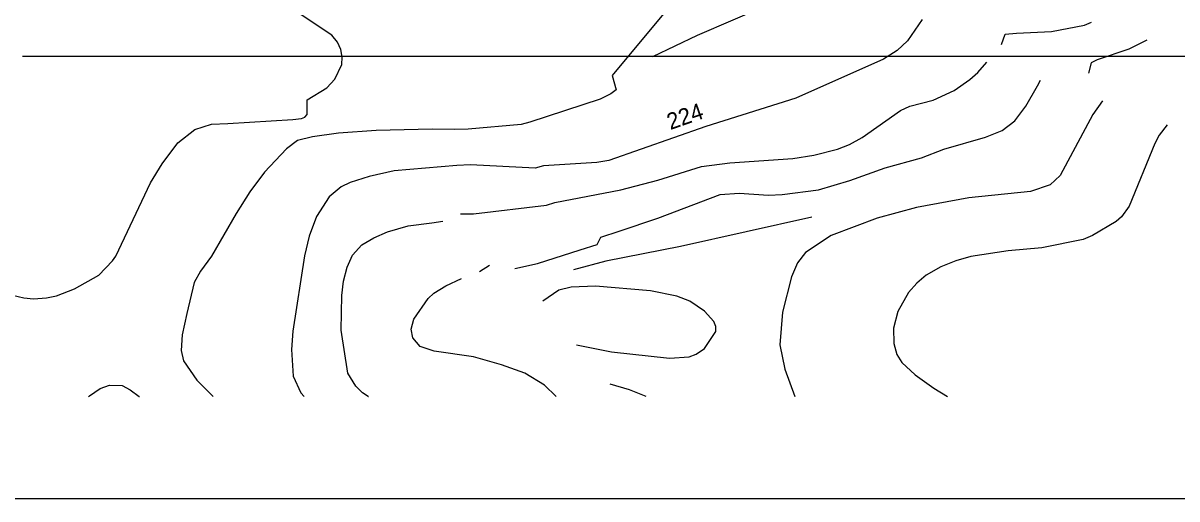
# Model space of a CAD drawing. Extents: x -662500 to -653478, y -1056827 to -1049993.
# Drawn here: x -659830 to -659128, y -1054269 to -1053980 of the extents above; entities that cross this region are included whole.
import ezdxf

# ---------------------------------------------------------------- set-up
doc = ezdxf.new("R2010")
doc.units = 0
for name, color, linetype in [('Vrstva 24', 7, 'Continuous'), ('Vrstva 7', 7, 'Continuous'), ('Vrstva 9', 7, 'Continuous')]:
    doc.layers.add(name, color=color, linetype=linetype)

msp = doc.modelspace()

# ---------------------------------------------------------------- linework, layer by layer
at = {"layer": 'Vrstva 24'}
for points in [[(-659446.58, -1054000), (-659419.5, -1053987), (-659376, -1053968.5), (-659341.5, -1053961)], [(-659446.58, -1054000), (-659830.33, -1054000)], [(-659029.99, -1054000), (-659446.58, -1054000)]]:
    msp.add_lwpolyline(points, dxfattribs=at)
at = {"layer": 'Vrstva 7'}
for p, q in [((-659431.99, -1053964.25), (-659471.32, -1054011.6)), ((-659642.01, -1053987.17), (-659674.04, -1053965.75)), ((-659282.58, -1053977.56), (-659291.58, -1053990.63)), ((-659183.94, -1053981.09), (-659179.67, -1053979.24)), ((-659234.42, -1053992.83), (-659232.23, -1053986.49)), ((-659232.23, -1053986.49), (-659225.23, -1053985.94)), ((-659225.23, -1053985.94), (-659203.88, -1053984.8)), ((-659203.88, -1053984.8), (-659183.94, -1053981.09)), ((-659638.56, -1053991.25), (-659642.01, -1053987.17)), ((-659636.59, -1053995.86), (-659638.56, -1053991.25)), ((-659291.58, -1053990.63), (-659297.85, -1053996.47)), ((-659146.03, -1053990.18), (-659156.89, -1053995.62)), ((-659635.74, -1054000.47), (-659636.59, -1053995.86)), ((-659635.8, -1054004.89), (-659635.74, -1054000.47)), ((-659297.85, -1053996.47), (-659306.11, -1054001.6)), ((-659156.89, -1053995.62), (-659176.06, -1054002.09)), ((-659640.2, -1054013.87), (-659635.8, -1054004.89)), ((-659306.11, -1054001.6), (-659359.64, -1054025.52)), ((-659248.87, -1054009.85), (-659243.29, -1054003.55)), ((-659179.83, -1054003.99), (-659181.53, -1054010.16)), ((-659176.06, -1054002.09), (-659179.83, -1054003.99)), ((-659645.06, -1054019.06), (-659640.2, -1054013.87)), ((-659471.32, -1054011.6), (-659468.87, -1054020.36)), ((-659263.11, -1054020.82), (-659253.57, -1054014.13)), ((-659253.57, -1054014.13), (-659248.87, -1054009.85)), ((-659212.46, -1054017.94), (-659210.61, -1054014.39)), ((-659656.96, -1054026.48), (-659645.06, -1054019.06)), ((-659468.87, -1054020.36), (-659472.12, -1054022.78)), ((-659275.92, -1054026.66), (-659263.11, -1054020.82)), ((-659219.54, -1054030.36), (-659212.46, -1054017.94)), ((-659656.92, -1054035.36), (-659656.96, -1054026.48)), ((-659478.72, -1054026.05), (-659521.42, -1054039.99)), ((-659472.12, -1054022.78), (-659478.72, -1054026.05)), ((-659359.64, -1054025.52), (-659414.32, -1054042.6)), ((-659290.16, -1054030.36), (-659275.92, -1054026.66)), ((-659172.97, -1054027.02), (-659178.82, -1054035.48)), ((-659658.39, -1054037.01), (-659656.92, -1054035.36)), ((-659319.2, -1054049.44), (-659295.85, -1054032.92)), ((-659295.85, -1054032.92), (-659290.16, -1054030.36)), ((-659226.37, -1054039.33), (-659219.54, -1054030.36)), ((-659178.82, -1054035.48), (-659198.61, -1054072.5)), ((-659725.31, -1054044.51), (-659715.27, -1054041.28)), ((-659715.27, -1054041.28), (-659705.34, -1054040.84)), ((-659705.34, -1054040.84), (-659665.75, -1054038.5)), ((-659665.75, -1054038.5), (-659660.47, -1054037.88)), ((-659660.47, -1054037.88), (-659658.39, -1054037.01)), ((-659526.81, -1054041.44), (-659559.09, -1054044.35)), ((-659521.42, -1054039.99), (-659526.81, -1054041.44)), ((-659414.32, -1054042.6), (-659473.37, -1054063.38)), ((-659233.92, -1054045.17), (-659226.37, -1054039.33)), ((-659133.6, -1054041.76), (-659138.38, -1054048.01)), ((-659735.79, -1054052.57), (-659725.31, -1054044.51)), ((-659653.8, -1054049.01), (-659662.91, -1054051.29)), ((-659637.85, -1054046.73), (-659653.8, -1054049.01)), ((-659615.07, -1054045.17), (-659637.85, -1054046.73)), ((-659580.9, -1054044.31), (-659615.07, -1054045.17)), ((-659567.44, -1054044.52), (-659580.9, -1054044.31)), ((-659559.09, -1054044.35), (-659567.44, -1054044.52)), ((-659326.89, -1054053.71), (-659319.2, -1054049.44)), ((-659269.51, -1054056.56), (-659244.03, -1054049.15)), ((-659244.03, -1054049.15), (-659233.92, -1054045.17)), ((-659138.38, -1054048.01), (-659141.09, -1054053.14)), ((-659745.28, -1054065.47), (-659735.79, -1054052.57)), ((-659669.6, -1054056.27), (-659682.99, -1054070.51)), ((-659662.91, -1054051.29), (-659669.6, -1054056.27)), ((-659348.54, -1054060.12), (-659334.3, -1054056.56)), ((-659334.3, -1054056.56), (-659326.89, -1054053.71)), ((-659283.04, -1054061.68), (-659269.51, -1054056.56)), ((-659141.09, -1054053.14), (-659156.61, -1054091.3)), ((-659473.37, -1054063.38), (-659480.66, -1054064.65)), ((-659399.79, -1054064.81), (-659361.35, -1054062.25)), ((-659361.35, -1054062.25), (-659348.54, -1054060.12)), ((-659305.25, -1054067.95), (-659283.04, -1054061.68)), ((-659752.36, -1054077.09), (-659745.28, -1054065.47)), ((-659682.99, -1054070.51), (-659691.79, -1054082.38)), ((-659603.97, -1054069.66), (-659619.34, -1054073.07)), ((-659565.93, -1054066.43), (-659603.97, -1054069.66)), ((-659557.66, -1054065.94), (-659565.93, -1054066.43)), ((-659518.28, -1054068.13), (-659557.66, -1054065.94)), ((-659513.11, -1054066.6), (-659518.28, -1054068.13)), ((-659480.66, -1054064.65), (-659513.11, -1054066.6)), ((-659443.65, -1054075.35), (-659416.88, -1054067.09)), ((-659416.88, -1054067.09), (-659399.79, -1054064.81)), ((-659326.61, -1054075.64), (-659305.25, -1054067.95)), ((-659773.34, -1054121.59), (-659752.36, -1054077.09)), ((-659630.73, -1054076.77), (-659636.29, -1054079.48)), ((-659619.34, -1054073.07), (-659630.73, -1054076.77)), ((-659466.14, -1054081.33), (-659443.65, -1054075.35)), ((-659345.69, -1054081.33), (-659326.61, -1054075.64)), ((-659198.61, -1054072.5), (-659204.73, -1054078.2)), ((-659691.79, -1054082.38), (-659700.22, -1054095.57)), ((-659636.29, -1054079.48), (-659643.55, -1054085.6)), ((-659506.19, -1054089.05), (-659466.14, -1054081.33)), ((-659443.5, -1054098.42), (-659405.63, -1054084.03)), ((-659405.63, -1054084.03), (-659394.1, -1054083.32)), ((-659394.1, -1054083.32), (-659376.16, -1054084.46)), ((-659376.16, -1054084.46), (-659367.9, -1054084.18)), ((-659367.9, -1054084.18), (-659345.69, -1054081.33)), ((-659216.69, -1054082.33), (-659254.28, -1054086.17)), ((-659204.73, -1054078.2), (-659216.69, -1054082.33)), ((-659643.55, -1054085.6), (-659651.24, -1054097.56)), ((-659555.67, -1054095.84), (-659511.35, -1054090.69)), ((-659511.35, -1054090.69), (-659506.19, -1054089.05)), ((-659254.28, -1054086.17), (-659286.17, -1054092.01)), ((-659156.61, -1054091.3), (-659161.31, -1054097.7)), ((-659700.22, -1054095.57), (-659715.18, -1054121.59)), ((-659651.24, -1054097.56), (-659655.79, -1054109.52)), ((-659563.56, -1054095.9), (-659555.67, -1054095.84)), ((-659467.07, -1054106.44), (-659443.5, -1054098.42)), ((-659349.82, -1054097.85), (-659429.69, -1054115.79)), ((-659310.09, -1054098.42), (-659338, -1054109.09)), ((-659286.17, -1054092.01), (-659310.09, -1054098.42)), ((-659161.31, -1054097.7), (-659164.58, -1054100.55)), ((-659608.1, -1054106.82), (-659595.42, -1054103.11)), ((-659595.42, -1054103.11), (-659581.19, -1054101.26)), ((-659581.19, -1054101.26), (-659574.44, -1054100.4)), ((-659164.58, -1054100.55), (-659179.1, -1054109.09)), ((-659655.79, -1054109.52), (-659658.64, -1054121.48)), ((-659623.76, -1054114.65), (-659616.5, -1054110.38)), ((-659616.5, -1054110.38), (-659608.1, -1054106.82)), ((-659480.55, -1054114.56), (-659478.32, -1054110.13)), ((-659478.32, -1054110.13), (-659467.07, -1054106.44)), ((-659338, -1054109.09), (-659353.66, -1054119.35)), ((-659184.66, -1054111.52), (-659209.86, -1054116.5)), ((-659179.1, -1054109.09), (-659184.66, -1054111.52)), ((-659629.31, -1054121.05), (-659623.76, -1054114.65)), ((-659516.83, -1054126.04), (-659490.92, -1054117.78)), ((-659490.92, -1054117.78), (-659480.55, -1054114.56)), ((-659429.69, -1054115.79), (-659475.26, -1054124.61)), ((-659353.66, -1054119.35), (-659358.65, -1054125.75)), ((-659230.36, -1054118.49), (-659253.14, -1054121.91)), ((-659209.86, -1054116.5), (-659230.36, -1054118.49)), ((-659783.83, -1054133.21), (-659775.46, -1054124.57)), ((-659775.46, -1054124.57), (-659773.34, -1054121.59)), ((-659715.18, -1054121.59), (-659721.91, -1054130.72)), ((-659658.64, -1054121.48), (-659665.62, -1054167.33)), ((-659632.58, -1054128.32), (-659629.31, -1054121.05)), ((-659530.64, -1054129.19), (-659516.83, -1054126.04)), ((-659475.26, -1054124.61), (-659494.97, -1054129.88)), ((-659358.65, -1054125.75), (-659362.2, -1054134.15)), ((-659262.25, -1054124.47), (-659271.37, -1054128.17)), ((-659253.14, -1054121.91), (-659262.25, -1054124.47)), ((-659798.57, -1054141.57), (-659783.83, -1054133.21)), ((-659721.91, -1054130.72), (-659725.67, -1054137.71)), ((-659634.86, -1054136.86), (-659632.58, -1054128.32)), ((-659552.12, -1054130.93), (-659546.03, -1054127.16)), ((-659280.19, -1054133.3), (-659285.89, -1054138.14)), ((-659271.37, -1054128.17), (-659280.19, -1054133.3)), ((-659725.67, -1054137.71), (-659730.28, -1054156.57)), ((-659635.86, -1054145.69), (-659634.86, -1054136.86)), ((-659579.9, -1054144.26), (-659572.64, -1054139.71)), ((-659572.64, -1054139.71), (-659563.14, -1054135.23)), ((-659496.33, -1054140.42), (-659503.73, -1054142.27)), ((-659481.52, -1054139.99), (-659496.33, -1054140.42)), ((-659447.92, -1054142.84), (-659481.52, -1054139.99)), ((-659362.2, -1054134.15), (-659367.61, -1054155.65)), ((-659285.89, -1054138.14), (-659291.01, -1054143.83)), ((-659836.26, -1054145.4), (-659829.46, -1054146.96)), ((-659829.46, -1054146.96), (-659823.51, -1054147.52)), ((-659823.51, -1054147.52), (-659815.57, -1054147.1)), ((-659815.57, -1054147.1), (-659809.48, -1054145.82)), ((-659809.48, -1054145.82), (-659798.57, -1054141.57)), ((-659636.29, -1054166.76), (-659635.86, -1054145.69)), ((-659592.15, -1054159.93), (-659583.32, -1054147.4)), ((-659583.32, -1054147.4), (-659579.9, -1054144.26)), ((-659503.73, -1054142.27), (-659513.62, -1054149.02)), ((-659431.97, -1054145.97), (-659447.92, -1054142.84)), ((-659424, -1054149.1), (-659431.97, -1054145.97)), ((-659291.01, -1054143.83), (-659297.56, -1054155.37)), ((-659415.17, -1054155.08), (-659424, -1054149.1)), ((-659409.47, -1054161.49), (-659415.17, -1054155.08)), ((-659730.28, -1054156.57), (-659733.09, -1054169.49)), ((-659593.71, -1054166.19), (-659592.15, -1054159.93)), ((-659408.19, -1054164.48), (-659409.47, -1054161.49)), ((-659367.61, -1054155.65), (-659369.32, -1054175.59)), ((-659297.56, -1054155.37), (-659300.15, -1054165.42)), ((-659665.62, -1054167.33), (-659666.61, -1054178.43)), ((-659632.3, -1054192.81), (-659636.29, -1054166.76)), ((-659592.58, -1054171.46), (-659593.71, -1054166.19)), ((-659415.17, -1054177.86), (-659408.19, -1054167.61)), ((-659408.19, -1054167.61), (-659408.19, -1054164.48)), ((-659300.15, -1054165.42), (-659299.84, -1054174.73)), ((-659733.09, -1054169.49), (-659733.77, -1054179.11)), ((-659588.31, -1054176.58), (-659592.58, -1054171.46)), ((-659493.11, -1054175.7), (-659471.84, -1054179.86)), ((-659369.32, -1054175.59), (-659366.19, -1054190.39)), ((-659299.84, -1054174.73), (-659298.13, -1054181.57)), ((-659733.77, -1054179.11), (-659732.32, -1054185.33)), ((-659666.61, -1054178.43), (-659665.47, -1054194.67)), ((-659579.76, -1054179.43), (-659588.31, -1054176.58)), ((-659555.84, -1054182.85), (-659579.76, -1054179.43)), ((-659538.76, -1054187.83), (-659555.84, -1054182.85)), ((-659471.84, -1054179.86), (-659436.53, -1054183.84)), ((-659436.53, -1054183.84), (-659424.57, -1054182.99)), ((-659424.57, -1054182.99), (-659420.3, -1054181.28)), ((-659420.3, -1054181.28), (-659415.17, -1054177.86)), ((-659298.13, -1054181.57), (-659295, -1054186.41)), ((-659732.32, -1054185.33), (-659724.19, -1054197.22)), ((-659524.52, -1054192.96), (-659538.76, -1054187.83)), ((-659295, -1054186.41), (-659287.03, -1054193.95)), ((-659724.19, -1054197.22), (-659714.21, -1054207.12)), ((-659665.47, -1054194.67), (-659660.78, -1054204.92)), ((-659627.32, -1054200.79), (-659632.3, -1054192.81)), ((-659512.55, -1054200.11), (-659524.52, -1054192.96)), ((-659366.19, -1054190.39), (-659360.17, -1054207.12)), ((-659287.03, -1054193.95), (-659275.64, -1054202.07)), ((-659789.49, -1054206.62), (-659782.98, -1054202.23)), ((-659782.98, -1054202.23), (-659777.31, -1054200.24)), ((-659777.31, -1054200.24), (-659769.66, -1054200.38)), ((-659769.66, -1054200.38), (-659764.76, -1054202.95)), ((-659764.76, -1054202.95), (-659759.17, -1054207.04)), ((-659623.33, -1054204.92), (-659627.32, -1054200.79)), ((-659505.36, -1054207.12), (-659512.55, -1054200.11)), ((-659460.73, -1054203.07), (-659472.64, -1054199.57)), ((-659450.73, -1054207.12), (-659460.73, -1054203.07)), ((-659275.64, -1054202.07), (-659267.32, -1054207.12)), ((-659790.07, -1054207.12), (-659789.49, -1054206.62)), ((-659759.17, -1054207.04), (-659759.11, -1054207.12)), ((-659660.78, -1054204.92), (-659658.9, -1054207.12)), ((-659619.91, -1054207.05), (-659623.33, -1054204.92)), ((-659619.91, -1054207.05), (-659619.75, -1054207.12))]:
    msp.add_line(p, q, dxfattribs=at)
at = {"layer": 'Vrstva 9'}
msp.add_line((-657221.63, -1054269.45), (-661971.63, -1054269.45), dxfattribs=at)

# ---------------------------------------------------------------- texts
at = {"layer": 'Vrstva 7'}
msp.add_text('224', height=10, rotation=19.38688, dxfattribs=at).set_placement((-659435.95, -1054044.91))

doc.saveas('drawing.dxf')
